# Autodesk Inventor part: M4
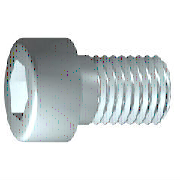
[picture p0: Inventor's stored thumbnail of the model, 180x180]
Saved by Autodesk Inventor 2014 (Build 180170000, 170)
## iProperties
IsCustomPart: 0
Company: 한국ATC센터
Created: 2014-10
Part Number: M4
Material: 강철
Description: 6각머리 태핑 나사
Document SubType Name: Modeling
Standard: KS B 1003
Designer: KYOUNG IL JANG
Standards Organization: KS
Language: ko-KR
Size Designation: M 4 x 10
Categories: <MemberInstance><Categories><Category DisplayName="조임쇠" InternalName="e4da775c-781d-43d5-af7c-5136215cf5a6" Mnemonic="FSTN"><Category DisplayName="볼트" InternalN
Density: 7.85 g/cm^3
Mass: 2.03451 g
Surface Area: 3.0572 cm^2
Volume: 0.259174 cm^3
Appearance: 검은색 캐스트
Author: KYOUNG IL JANG
Revision Number: 1
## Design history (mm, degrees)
sketch "스케치1"
  geometry: L1 (-1, 0)-(10, 0); L2 (10, 0)-(10, 2); L3 (10, 2)-(1.75, 2); L4 (1.75, 2)-(1.32, 2); L5 (1.32, 2)-(0, 2); L6 (0, 2)-(0, 3.5); L7 (0, 3.5)-(-4, 3.5); L8 (-4, 3.5)-(-4, 1.732); L9 (-4, 1.732)-(-2, 1.732); L10 (-2, 1.732)-(-1, 0); L11 (-6.8, 0)-(12.8, 0) reference; L12 (0, -0.7)-(0, 4.2) reference; L13 (1.75, 2)-(0, 2)
  constraints: 22 end point, 6 parallel, 2 collinear, 2 perpendicular, 1 horizontal, 1 point on line
  dimensions: "d1" = 8.25 distance from line of L3.end L2 (= GEL); "d2" = 0.42952 distance of L4.end L3.end (computed from GAL); "d3" = 4 distance between parallel lines of L8 L6 (= KOH); "d4" = 2 distance of L8.end L9.end (= INTI); "d5" = 60 deg angle of L10 L1; "d6" = 4 diameter of L3 L1 (= GD); "d7" = 4 diameter of L5 L1 (= BDM); "d8" = 3.4641 diameter of L9 L1 (= 1.1547 x SW); "d9" = 7 diameter of L7 L1 (= KOD); "d26" = 10 distance between parallel lines of L12 L2 (= NLG)
revolve "본체" sketch "스케치1" stored, may be unused: angle "d10" = 90 deg
sketch "스케치2"
  geometry: L1 (0, -4.9)-(0, 4.9) reference; L2 (-4.9, 0)-(4.9, 0) reference; L3 (1.732, 0)-(0.866, -1.5); L4 (0.866, -1.5)-(-0.866, -1.5); L5 (-0.866, -1.5)-(-1.732, 0); L6 (-1.732, 0)-(-0.866, 1.5); L7 (-0.866, 1.5)-(0.866, 1.5); L8 (0.866, 1.5)-(1.732, 0); 2 further points
  constraints: 12 end point, 1 coincident, 1 horizontal alignment, 1 point on line, 12 other
extrude "슬롯" join sketch "스케치2" stored distance "d11" = 10; taper "d12" = 0 deg
workplane "Work Plane1"
fillet "Fillet2" dims "d30" = 0.1 (= R)
body "Solid1"
fillet "모깎기1" dims "d17" = 0.4 (= RR)
feature "스레드" dims "d13" = 8.25 (= GEL), "d14" = 0
chamfer "모따기1" distance "d15" = 0.42941 (= -0.5 x SPD + 0.5 x GD); stored, may be unused: second distance "d16" = 0.42941 (= GUL), angle "d27" = 45 deg
other parameters: "GD" = 4 (= NND) [user parameter; used in 2 equation terms], "NLG" = 10 [user parameter; used in 1 equation term], "GEL" = 8.25 [user parameter; used in 2 equation terms], "KOD" = 7 [user parameter; used in 1 equation term], "KOH" = 4 [user parameter; used in 1 equation term], "INTI" = 2 [user parameter; used in 1 equation term], "GAL" = 0.42941 (= 0.61345 x PTC) [user parameter; used in 1 equation term], "GUL" = 0.42941 (= 0.61345 x PTC) [user parameter; used in 1 equation term], "BDM" = 4 (= NND) [user parameter; used in 1 equation term], "SW" = 3 [user parameter; used in 2 equation terms], "RR" = 0.4 [user parameter; used in 1 equation term], "SPD" = 3.14117 (= NND - 1.2269 x PTC) [user parameter; used in 1 equation term], "d19" = 0, "d28" = 0, "d29" = 0, "R" = 0.1 [user parameter; used in 1 equation term], "PHH" = 0.2 [user parameter], "GD1" = 3.14117 (= THREADDIA - 1.2269 x PTC) [user parameter], "THREADDIA" = 4 [user parameter; used in 1 equation term], "FAWI" = 45 deg [user parameter], "TPU" = 14.28571 (computed from PTC) [user parameter], "PTC" = 0.7 [user parameter; used in 5 equation terms], "NND" = 4 [user parameter; used in 3 equation terms], "TOA" = 30 deg [user parameter], "E0" = 3.465 (= 1.155 x SW) [user parameter]
